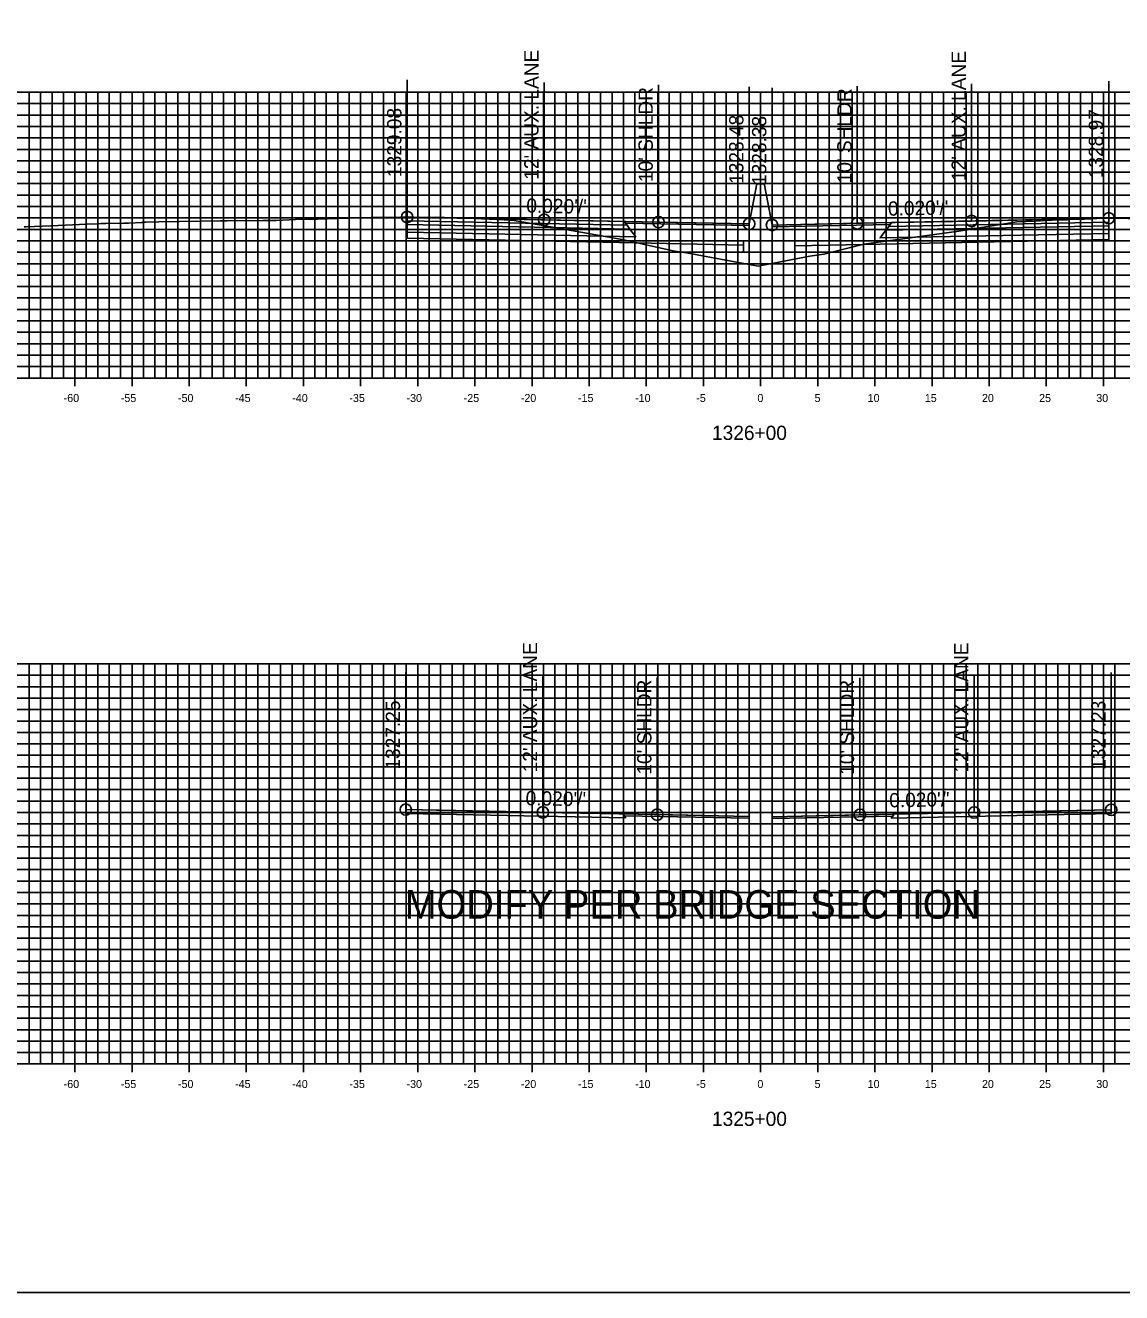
# Model space of a CAD drawing. Extents: x 674939 to 678919, y 750652 to 765176.
# Drawn here: x 678674.2 to 678770.1, y 751612.6 to 751723.4 of the extents above; entities that cross this region are included whole.
import ezdxf

# ---------------------------------------------------------------- set-up
doc = ezdxf.new("R2010")
doc.units = 0
for name, color, linetype in [('R_Alt Surface', 7, 'Continuous'), ('R_Axis', 7, 'Continuous'), ('R_Axis Annot', 7, 'Continuous'), ('R_Exist Surface', 7, 'Continuous'), ('R_Fin Surface', 7, 'Continuous'), ('R_Grid', 7, 'Continuous'), ('R_No Plot', 7, 'Continuous'), ('R_Proposed Road', 7, 'Continuous'), ('R_Xsect Elev', 7, 'Continuous'), ('R_Xsect Slope', 7, 'Continuous')]:
    doc.layers.add(name, color=color, linetype=linetype)

msp = doc.modelspace()

# ---------------------------------------------------------------- linework, layer by layer
at = {"layer": 'R_Alt Surface'}
for points in [[(678707.6, 751706.3), (678707.6, 751705.97), (678727.1, 751705.58), (678726.85, 751705.92)], [(678707.6, 751705.97), (678707.6, 751705.31), (678727.6, 751704.91), (678727.1, 751705.58)], [(678768.99, 751705.86), (678768.99, 751705.2), (678748.99, 751704.8), (678749.49, 751705.47)], [(678768.99, 751706.19), (678768.99, 751705.86), (678749.49, 751705.47), (678749.74, 751705.81)]]:
    msp.add_lwpolyline(points, close=True, dxfattribs=at)
for points in [[(678707.6, 751705.31), (678707.6, 751704.77), (678727.6, 751704.37), (678737.03, 751704.18)], [(678768.99, 751705.2), (678768.99, 751704.66), (678748.99, 751704.26), (678741.53, 751704.11)]]:
    msp.add_lwpolyline(points, dxfattribs=at)
at = {"layer": 'R_Axis'}
for p, q in [((678638.53, 751692.55), (678838.53, 751692.55)), ((678678.53, 751691.85), (678678.53, 751693.25)), ((678683.53, 751691.85), (678683.53, 751693.25)), ((678688.53, 751691.85), (678688.53, 751693.25)), ((678693.53, 751691.85), (678693.53, 751693.25)), ((678698.53, 751691.85), (678698.53, 751693.25)), ((678703.53, 751691.85), (678703.53, 751693.25)), ((678708.53, 751691.85), (678708.53, 751693.25)), ((678713.53, 751691.85), (678713.53, 751693.25)), ((678718.53, 751691.85), (678718.53, 751693.25)), ((678723.53, 751691.85), (678723.53, 751693.25)), ((678728.53, 751691.85), (678728.53, 751693.25)), ((678733.53, 751691.85), (678733.53, 751693.25)), ((678738.53, 751691.85), (678738.53, 751693.25)), ((678743.53, 751691.85), (678743.53, 751693.25)), ((678748.53, 751691.85), (678748.53, 751693.25)), ((678753.53, 751691.85), (678753.53, 751693.25)), ((678758.53, 751691.85), (678758.53, 751693.25)), ((678763.53, 751691.85), (678763.53, 751693.25)), ((678768.53, 751691.85), (678768.53, 751693.25)), ((678638.53, 751632.55), (678838.53, 751632.55)), ((678678.53, 751631.85), (678678.53, 751633.25)), ((678683.53, 751631.85), (678683.53, 751633.25)), ((678688.53, 751631.85), (678688.53, 751633.25)), ((678693.53, 751631.85), (678693.53, 751633.25)), ((678698.53, 751631.85), (678698.53, 751633.25)), ((678703.53, 751631.85), (678703.53, 751633.25)), ((678708.53, 751631.85), (678708.53, 751633.25)), ((678713.53, 751631.85), (678713.53, 751633.25)), ((678718.53, 751631.85), (678718.53, 751633.25)), ((678723.53, 751631.85), (678723.53, 751633.25)), ((678728.53, 751631.85), (678728.53, 751633.25)), ((678733.53, 751631.85), (678733.53, 751633.25)), ((678738.53, 751631.85), (678738.53, 751633.25)), ((678743.53, 751631.85), (678743.53, 751633.25)), ((678748.53, 751631.85), (678748.53, 751633.25)), ((678753.53, 751631.85), (678753.53, 751633.25)), ((678758.53, 751631.85), (678758.53, 751633.25)), ((678763.53, 751631.85), (678763.53, 751633.25)), ((678768.53, 751631.85), (678768.53, 751633.25))]:
    msp.add_line(p, q, dxfattribs=at)
at = {"layer": 'R_Exist Surface'}
msp.add_lwpolyline([(678674.1, 751705.78), (678674.26, 751705.76), (678674.27, 751705.76), (678676.43, 751705.85), (678677.71, 751705.91), (678679.56, 751706), (678680.49, 751706.03), (678680.8, 751706.05), (678681.25, 751706.06), (678682.8, 751706.09), (678683.21, 751706.09), (678684.43, 751706.16), (678684.47, 751706.17), (678684.61, 751706.18), (678684.78, 751706.19), (678685.87, 751706.21), (678691.28, 751706.3), (678691.87, 751706.31), (678694.96, 751706.33), (678695.82, 751706.33), (678695.92, 751706.33), (678696.14, 751706.34), (678697.84, 751706.42), (678698.52, 751706.43), (678699.76, 751706.45), (678703.32, 751706.55), (678704.45, 751706.58), (678707.06, 751706.62), (678707.6, 751706.63), (678707.65, 751706.63), (678707.98, 751706.64), (678708.16, 751706.63), (678708.63, 751706.6), (678709.71, 751706.6), (678710.07, 751706.61), (678711.71, 751706.56), (678712.16, 751706.56), (678716.09, 751706.39), (678716.98, 751706.34), (678720.98, 751705.64), (678726.41, 751704.67), (678730.88, 751703.67), (678732.2, 751703.48), (678738.33, 751702.34), (678742.85, 751703.22), (678744.07, 751703.38), (678747.55, 751704.26), (678755.88, 751705.39), (678760.94, 751706.22), (678762.53, 751706.28), (678764.56, 751706.39), (678764.86, 751706.39), (678765.36, 751706.39), (678765.56, 751706.41), (678765.96, 751706.43), (678766.86, 751706.45), (678767.46, 751706.48), (678767.96, 751706.51), (678768.36, 751706.53), (678768.67, 751706.53), (678768.99, 751706.52), (678772.38, 751706.47)], dxfattribs=at)
at = {"layer": 'R_Fin Surface'}
for points in [[(678737.53, 751706.03), (678729.6, 751706.19), (678719.6, 751706.39), (678707.6, 751706.63)], [(678768.99, 751706.52), (678756.99, 751706.28), (678746.99, 751706.08), (678739.53, 751705.93)], [(678737.53, 751654.2), (678729.48, 751654.36), (678719.48, 751654.56), (678707.48, 751654.8)], [(678769.21, 751654.78), (678757.21, 751654.54), (678747.21, 751654.34), (678739.53, 751654.18)]]:
    msp.add_lwpolyline(points, dxfattribs=at)
for points in [[(678707.6, 751706.63), (678707.6, 751706.3), (678726.85, 751705.92), (678726.6, 751706.25)], [(678726.6, 751706.25), (678737.53, 751706.03), (678737.54, 751705.88), (678726.72, 751706.09)], [(678749.87, 751705.98), (678739.53, 751705.78), (678739.53, 751705.93), (678749.99, 751706.14)], [(678768.99, 751706.52), (678768.99, 751706.19), (678749.74, 751705.81), (678749.99, 751706.14)], [(678707.48, 751654.8), (678707.48, 751654.47), (678726.73, 751654.09), (678726.48, 751654.42)], [(678769.21, 751654.78), (678769.21, 751654.45), (678749.96, 751654.06), (678750.21, 751654.4)], [(678726.48, 751654.42), (678737.53, 751654.2), (678737.54, 751654.04), (678726.6, 751654.26)], [(678750.09, 751654.24), (678739.53, 751654.03), (678739.53, 751654.18), (678750.21, 751654.4)]]:
    msp.add_lwpolyline(points, close=True, dxfattribs=at)
at = {"layer": 'R_Grid'}
for p, q in [((678638.53, 751717.55), (678838.53, 751717.55)), ((678674.53, 751692.55), (678674.53, 751717.55)), ((678675.53, 751692.55), (678675.53, 751717.55)), ((678676.53, 751692.55), (678676.53, 751717.55)), ((678677.53, 751692.55), (678677.53, 751717.55)), ((678678.53, 751692.55), (678678.53, 751717.55)), ((678679.53, 751692.55), (678679.53, 751717.55)), ((678680.53, 751692.55), (678680.53, 751717.55)), ((678681.53, 751692.55), (678681.53, 751717.55)), ((678682.53, 751692.55), (678682.53, 751717.55)), ((678683.53, 751692.55), (678683.53, 751717.55)), ((678684.53, 751692.55), (678684.53, 751717.55)), ((678685.53, 751692.55), (678685.53, 751717.55)), ((678686.53, 751692.55), (678686.53, 751717.55)), ((678687.53, 751692.55), (678687.53, 751717.55)), ((678688.53, 751692.55), (678688.53, 751717.55)), ((678689.53, 751692.55), (678689.53, 751717.55)), ((678690.53, 751692.55), (678690.53, 751717.55)), ((678691.53, 751692.55), (678691.53, 751717.55)), ((678692.53, 751692.55), (678692.53, 751717.55)), ((678693.53, 751692.55), (678693.53, 751717.55)), ((678694.53, 751692.55), (678694.53, 751717.55)), ((678695.53, 751692.55), (678695.53, 751717.55)), ((678696.53, 751692.55), (678696.53, 751717.55)), ((678697.53, 751692.55), (678697.53, 751717.55)), ((678698.53, 751692.55), (678698.53, 751717.55)), ((678699.53, 751692.55), (678699.53, 751717.55)), ((678700.53, 751692.55), (678700.53, 751717.55)), ((678701.53, 751692.55), (678701.53, 751717.55)), ((678702.53, 751692.55), (678702.53, 751717.55)), ((678703.53, 751692.55), (678703.53, 751717.55)), ((678704.53, 751692.55), (678704.53, 751717.55)), ((678705.53, 751692.55), (678705.53, 751717.55)), ((678706.53, 751692.55), (678706.53, 751717.55)), ((678707.53, 751692.55), (678707.53, 751717.55)), ((678708.53, 751692.55), (678708.53, 751717.55)), ((678709.53, 751692.55), (678709.53, 751717.55)), ((678710.53, 751692.55), (678710.53, 751717.55)), ((678711.53, 751692.55), (678711.53, 751717.55)), ((678712.53, 751692.55), (678712.53, 751717.55)), ((678713.53, 751692.55), (678713.53, 751717.55)), ((678714.53, 751692.55), (678714.53, 751717.55)), ((678715.53, 751692.55), (678715.53, 751717.55)), ((678716.53, 751692.55), (678716.53, 751717.55)), ((678717.53, 751692.55), (678717.53, 751717.55)), ((678718.53, 751692.55), (678718.53, 751717.55)), ((678719.53, 751692.55), (678719.53, 751717.55)), ((678720.53, 751692.55), (678720.53, 751717.55)), ((678721.53, 751692.55), (678721.53, 751717.55)), ((678722.53, 751692.55), (678722.53, 751717.55)), ((678723.53, 751692.55), (678723.53, 751717.55)), ((678724.53, 751692.55), (678724.53, 751717.55)), ((678725.53, 751692.55), (678725.53, 751717.55)), ((678726.53, 751692.55), (678726.53, 751717.55)), ((678727.53, 751692.55), (678727.53, 751717.55)), ((678728.53, 751692.55), (678728.53, 751717.55)), ((678729.53, 751692.55), (678729.53, 751717.55)), ((678730.53, 751692.55), (678730.53, 751717.55)), ((678731.53, 751692.55), (678731.53, 751717.55)), ((678732.53, 751692.55), (678732.53, 751717.55)), ((678733.53, 751692.55), (678733.53, 751717.55)), ((678734.53, 751692.55), (678734.53, 751717.55)), ((678735.53, 751692.55), (678735.53, 751717.55)), ((678736.53, 751692.55), (678736.53, 751717.55)), ((678737.53, 751692.55), (678737.53, 751717.55)), ((678738.53, 751692.55), (678738.53, 751717.55)), ((678739.53, 751692.55), (678739.53, 751717.55)), ((678740.53, 751692.55), (678740.53, 751717.55)), ((678741.53, 751692.55), (678741.53, 751717.55)), ((678742.53, 751692.55), (678742.53, 751717.55)), ((678743.53, 751692.55), (678743.53, 751717.55)), ((678744.53, 751692.55), (678744.53, 751717.55)), ((678745.53, 751692.55), (678745.53, 751717.55)), ((678746.53, 751692.55), (678746.53, 751717.55)), ((678747.53, 751692.55), (678747.53, 751717.55)), ((678748.53, 751692.55), (678748.53, 751717.55)), ((678749.53, 751692.55), (678749.53, 751717.55)), ((678750.53, 751692.55), (678750.53, 751717.55)), ((678751.53, 751692.55), (678751.53, 751717.55)), ((678752.53, 751692.55), (678752.53, 751717.55)), ((678753.53, 751692.55), (678753.53, 751717.55)), ((678754.53, 751692.55), (678754.53, 751717.55)), ((678755.53, 751692.55), (678755.53, 751717.55)), ((678756.53, 751692.55), (678756.53, 751717.55)), ((678757.53, 751692.55), (678757.53, 751717.55)), ((678758.53, 751692.55), (678758.53, 751717.55)), ((678759.53, 751692.55), (678759.53, 751717.55)), ((678760.53, 751692.55), (678760.53, 751717.55)), ((678761.53, 751692.55), (678761.53, 751717.55)), ((678762.53, 751692.55), (678762.53, 751717.55)), ((678763.53, 751692.55), (678763.53, 751717.55)), ((678764.53, 751692.55), (678764.53, 751717.55)), ((678765.53, 751692.55), (678765.53, 751717.55)), ((678766.53, 751692.55), (678766.53, 751717.55)), ((678767.53, 751692.55), (678767.53, 751717.55)), ((678768.53, 751692.55), (678768.53, 751717.55)), ((678769.53, 751692.55), (678769.53, 751717.55)), ((678638.53, 751716.55), (678838.53, 751716.55)), ((678638.53, 751715.55), (678838.53, 751715.55)), ((678638.53, 751714.55), (678838.53, 751714.55)), ((678638.53, 751713.55), (678838.53, 751713.55)), ((678638.53, 751712.55), (678838.53, 751712.55)), ((678638.53, 751711.55), (678838.53, 751711.55)), ((678638.53, 751710.55), (678838.53, 751710.55)), ((678638.53, 751709.55), (678838.53, 751709.55)), ((678638.53, 751708.55), (678838.53, 751708.55)), ((678638.53, 751707.55), (678838.53, 751707.55)), ((678638.53, 751706.55), (678838.53, 751706.55)), ((678638.53, 751705.55), (678838.53, 751705.55)), ((678638.53, 751704.55), (678838.53, 751704.55)), ((678638.53, 751703.55), (678838.53, 751703.55)), ((678638.53, 751702.55), (678838.53, 751702.55)), ((678638.53, 751701.55), (678838.53, 751701.55)), ((678638.53, 751700.55), (678838.53, 751700.55)), ((678638.53, 751699.55), (678838.53, 751699.55)), ((678638.53, 751698.55), (678838.53, 751698.55)), ((678638.53, 751697.55), (678838.53, 751697.55)), ((678638.53, 751696.55), (678838.53, 751696.55)), ((678638.53, 751695.55), (678838.53, 751695.55)), ((678638.53, 751694.55), (678838.53, 751694.55)), ((678638.53, 751693.55), (678838.53, 751693.55)), ((678638.53, 751692.55), (678838.53, 751692.55)), ((678638.53, 751667.55), (678838.53, 751667.55)), ((678674.53, 751632.55), (678674.53, 751667.55)), ((678675.53, 751632.55), (678675.53, 751667.55)), ((678676.53, 751632.55), (678676.53, 751667.55)), ((678677.53, 751632.55), (678677.53, 751667.55)), ((678678.53, 751632.55), (678678.53, 751667.55)), ((678679.53, 751632.55), (678679.53, 751667.55)), ((678680.53, 751632.55), (678680.53, 751667.55)), ((678681.53, 751632.55), (678681.53, 751667.55)), ((678682.53, 751632.55), (678682.53, 751667.55)), ((678683.53, 751632.55), (678683.53, 751667.55)), ((678684.53, 751632.55), (678684.53, 751667.55)), ((678685.53, 751632.55), (678685.53, 751667.55)), ((678686.53, 751632.55), (678686.53, 751667.55)), ((678687.53, 751632.55), (678687.53, 751667.55)), ((678688.53, 751632.55), (678688.53, 751667.55)), ((678689.53, 751632.55), (678689.53, 751667.55)), ((678690.53, 751632.55), (678690.53, 751667.55)), ((678691.53, 751632.55), (678691.53, 751667.55)), ((678692.53, 751632.55), (678692.53, 751667.55)), ((678693.53, 751632.55), (678693.53, 751667.55)), ((678694.53, 751632.55), (678694.53, 751667.55)), ((678695.53, 751632.55), (678695.53, 751667.55)), ((678696.53, 751632.55), (678696.53, 751667.55)), ((678697.53, 751632.55), (678697.53, 751667.55)), ((678698.53, 751632.55), (678698.53, 751667.55)), ((678699.53, 751632.55), (678699.53, 751667.55)), ((678700.53, 751632.55), (678700.53, 751667.55)), ((678701.53, 751632.55), (678701.53, 751667.55)), ((678702.53, 751632.55), (678702.53, 751667.55)), ((678703.53, 751632.55), (678703.53, 751667.55)), ((678704.53, 751632.55), (678704.53, 751667.55)), ((678705.53, 751632.55), (678705.53, 751667.55)), ((678706.53, 751632.55), (678706.53, 751667.55)), ((678707.53, 751632.55), (678707.53, 751667.55)), ((678708.53, 751632.55), (678708.53, 751667.55)), ((678709.53, 751632.55), (678709.53, 751667.55)), ((678710.53, 751632.55), (678710.53, 751667.55)), ((678711.53, 751632.55), (678711.53, 751667.55)), ((678712.53, 751632.55), (678712.53, 751667.55)), ((678713.53, 751632.55), (678713.53, 751667.55)), ((678714.53, 751632.55), (678714.53, 751667.55)), ((678715.53, 751632.55), (678715.53, 751667.55)), ((678716.53, 751632.55), (678716.53, 751667.55)), ((678717.53, 751632.55), (678717.53, 751667.55)), ((678718.53, 751632.55), (678718.53, 751667.55)), ((678719.53, 751632.55), (678719.53, 751667.55)), ((678720.53, 751632.55), (678720.53, 751667.55)), ((678721.53, 751632.55), (678721.53, 751667.55)), ((678722.53, 751632.55), (678722.53, 751667.55)), ((678723.53, 751632.55), (678723.53, 751667.55)), ((678724.53, 751632.55), (678724.53, 751667.55)), ((678725.53, 751632.55), (678725.53, 751667.55)), ((678726.53, 751632.55), (678726.53, 751667.55)), ((678727.53, 751632.55), (678727.53, 751667.55)), ((678728.53, 751632.55), (678728.53, 751667.55)), ((678729.53, 751632.55), (678729.53, 751667.55)), ((678730.53, 751632.55), (678730.53, 751667.55)), ((678731.53, 751632.55), (678731.53, 751667.55)), ((678732.53, 751632.55), (678732.53, 751667.55)), ((678733.53, 751632.55), (678733.53, 751667.55)), ((678734.53, 751632.55), (678734.53, 751667.55)), ((678735.53, 751632.55), (678735.53, 751667.55)), ((678736.53, 751632.55), (678736.53, 751667.55)), ((678737.53, 751632.55), (678737.53, 751667.55)), ((678738.53, 751632.55), (678738.53, 751667.55)), ((678739.53, 751632.55), (678739.53, 751667.55)), ((678740.53, 751632.55), (678740.53, 751667.55)), ((678741.53, 751632.55), (678741.53, 751667.55)), ((678742.53, 751632.55), (678742.53, 751667.55)), ((678743.53, 751632.55), (678743.53, 751667.55)), ((678744.53, 751632.55), (678744.53, 751667.55)), ((678745.53, 751632.55), (678745.53, 751667.55)), ((678746.53, 751632.55), (678746.53, 751667.55)), ((678747.53, 751632.55), (678747.53, 751667.55)), ((678748.53, 751632.55), (678748.53, 751667.55)), ((678749.53, 751632.55), (678749.53, 751667.55)), ((678750.53, 751632.55), (678750.53, 751667.55)), ((678751.53, 751632.55), (678751.53, 751667.55)), ((678752.53, 751632.55), (678752.53, 751667.55)), ((678753.53, 751632.55), (678753.53, 751667.55)), ((678754.53, 751632.55), (678754.53, 751667.55)), ((678755.53, 751632.55), (678755.53, 751667.55)), ((678756.53, 751632.55), (678756.53, 751667.55)), ((678757.53, 751632.55), (678757.53, 751667.55)), ((678758.53, 751632.55), (678758.53, 751667.55)), ((678759.53, 751632.55), (678759.53, 751667.55)), ((678760.53, 751632.55), (678760.53, 751667.55)), ((678761.53, 751632.55), (678761.53, 751667.55)), ((678762.53, 751632.55), (678762.53, 751667.55)), ((678763.53, 751632.55), (678763.53, 751667.55)), ((678764.53, 751632.55), (678764.53, 751667.55)), ((678765.53, 751632.55), (678765.53, 751667.55)), ((678766.53, 751632.55), (678766.53, 751667.55)), ((678767.53, 751632.55), (678767.53, 751667.55)), ((678768.53, 751632.55), (678768.53, 751667.55)), ((678769.53, 751632.55), (678769.53, 751667.55)), ((678638.53, 751666.55), (678838.53, 751666.55)), ((678638.53, 751665.55), (678838.53, 751665.55)), ((678638.53, 751664.55), (678838.53, 751664.55)), ((678638.53, 751663.55), (678838.53, 751663.55)), ((678638.53, 751662.55), (678838.53, 751662.55)), ((678638.53, 751661.55), (678838.53, 751661.55)), ((678638.53, 751660.55), (678838.53, 751660.55)), ((678638.53, 751659.55), (678838.53, 751659.55)), ((678638.53, 751658.55), (678838.53, 751658.55)), ((678638.53, 751657.55), (678838.53, 751657.55)), ((678638.53, 751656.55), (678838.53, 751656.55)), ((678638.53, 751655.55), (678838.53, 751655.55)), ((678638.53, 751654.55), (678838.53, 751654.55)), ((678638.53, 751653.55), (678838.53, 751653.55)), ((678638.53, 751652.55), (678838.53, 751652.55)), ((678638.53, 751651.55), (678838.53, 751651.55)), ((678638.53, 751650.55), (678838.53, 751650.55)), ((678638.53, 751649.55), (678838.53, 751649.55)), ((678638.53, 751648.55), (678838.53, 751648.55)), ((678638.53, 751647.55), (678838.53, 751647.55)), ((678638.53, 751646.55), (678838.53, 751646.55)), ((678638.53, 751645.55), (678838.53, 751645.55)), ((678638.53, 751644.55), (678838.53, 751644.55)), ((678638.53, 751643.55), (678838.53, 751643.55)), ((678638.53, 751642.55), (678838.53, 751642.55)), ((678638.53, 751641.55), (678838.53, 751641.55)), ((678638.53, 751640.55), (678838.53, 751640.55)), ((678638.53, 751639.55), (678838.53, 751639.55)), ((678638.53, 751638.55), (678838.53, 751638.55)), ((678638.53, 751637.55), (678838.53, 751637.55)), ((678638.53, 751636.55), (678838.53, 751636.55)), ((678638.53, 751635.55), (678838.53, 751635.55)), ((678638.53, 751634.55), (678838.53, 751634.55)), ((678638.53, 751633.55), (678838.53, 751633.55)), ((678638.53, 751632.55), (678838.53, 751632.55))]:
    msp.add_line(p, q, dxfattribs=at)
at = {"layer": 'R_No Plot'}
msp.add_lwpolyline([(678578.53, 751612.55), (678918.53, 751612.55), (678918.53, 751832.55), (678578.53, 751832.55)], close=True, dxfattribs=at)
for centre in [(678707.6, 751706.63), (678719.6, 751706.39), (678756.99, 751706.28), (678768.99, 751706.52), (678729.6, 751706.19), (678737.53, 751706.03), (678739.53, 751705.93), (678746.99, 751706.08), (678707.48, 751654.8), (678719.48, 751654.56), (678729.48, 751654.36), (678747.21, 751654.34), (678757.21, 751654.54), (678769.21, 751654.78)]:
    msp.add_circle(centre, 0.5, dxfattribs=at)
at = {"layer": 'R_Proposed Road'}
for points in [[(678738.2, 751709.53), (678737.53, 751706.03)], [(678738.86, 751709.43), (678738.86, 751709.53), (678738.2, 751709.53), (678738.2, 751709.53)], [(678738.86, 751709.43), (678739.53, 751705.93)], [(678737.53, 751706.03), (678737.53, 751704.56), (678737.03, 751704.56), (678737.03, 751703.56), (678741.53, 751703.56), (678741.53, 751704.56), (678739.53, 751704.56), (678739.53, 751705.93)]]:
    msp.add_lwpolyline(points, dxfattribs=at)
at = {"layer": 'R_Xsect Elev'}
for p, q in [((678707.6, 751706.63), (678707.6, 751718.63)), ((678719.6, 751706.39), (678719.6, 751718.39)), ((678729.6, 751706.19), (678729.6, 751718.19)), ((678737.53, 751706.03), (678737.53, 751718.03)), ((678739.53, 751705.93), (678739.53, 751717.93)), ((678746.99, 751706.08), (678746.99, 751718.08)), ((678756.99, 751706.28), (678756.99, 751718.28)), ((678768.99, 751706.52), (678768.99, 751718.52)), ((678707.48, 751654.8), (678707.48, 751666.8)), ((678719.48, 751654.56), (678719.48, 751666.56)), ((678729.48, 751654.36), (678729.48, 751666.36)), ((678747.21, 751654.34), (678747.21, 751666.34)), ((678757.21, 751654.54), (678757.21, 751666.54)), ((678769.21, 751654.78), (678769.21, 751666.78))]:
    msp.add_line(p, q, dxfattribs=at)

# ---------------------------------------------------------------- texts
at = {"layer": 'R_Axis Annot'}
for s, height, p in [('-60', 0.7, (678677.55, 751690.45)), ('-55', 0.7, (678682.55, 751690.45)), ('-50', 0.7, (678687.55, 751690.45)), ('-45', 0.7, (678692.55, 751690.45)), ('-40', 0.7, (678697.55, 751690.45)), ('-35', 0.7, (678702.55, 751690.45)), ('-30', 0.7, (678707.55, 751690.45)), ('-25', 0.7, (678712.55, 751690.45)), ('-20', 0.7, (678717.55, 751690.45)), ('-15', 0.7, (678722.55, 751690.45)), ('-10', 0.7, (678727.55, 751690.45)), ('-5', 0.7, (678732.9, 751690.45)), ('0', 0.7, (678738.25, 751690.45)), ('5', 0.7, (678743.25, 751690.45)), ('10', 0.7, (678747.9, 751690.45)), ('15', 0.7, (678752.9, 751690.45)), ('20', 0.7, (678757.9, 751690.45)), ('25', 0.7, (678762.9, 751690.45)), ('30', 0.7, (678767.9, 751690.45)), ('1326+00', 1.25, (678734.28, 751687.13)), ('-60', 0.7, (678677.55, 751630.45)), ('-55', 0.7, (678682.55, 751630.45)), ('-50', 0.7, (678687.55, 751630.45)), ('-45', 0.7, (678692.55, 751630.45)), ('-40', 0.7, (678697.55, 751630.45)), ('-35', 0.7, (678702.55, 751630.45)), ('-30', 0.7, (678707.55, 751630.45)), ('-25', 0.7, (678712.55, 751630.45)), ('-20', 0.7, (678717.55, 751630.45)), ('-15', 0.7, (678722.55, 751630.45)), ('-10', 0.7, (678727.55, 751630.45)), ('-5', 0.7, (678732.9, 751630.45)), ('0', 0.7, (678738.25, 751630.45)), ('5', 0.7, (678743.25, 751630.45)), ('10', 0.7, (678747.9, 751630.45)), ('15', 0.7, (678752.9, 751630.45)), ('20', 0.7, (678757.9, 751630.45)), ('25', 0.7, (678762.9, 751630.45)), ('30', 0.7, (678767.9, 751630.45)), ('1325+00', 1.25, (678734.28, 751627.13))]:
    msp.add_text(s, height=height, dxfattribs=at).set_placement(p)
at = {"layer": 'R_Xsect Elev'}
for s, p in [("12' AUX. LANE", (678719.1, 751709.89)), ("12' AUX. LANE", (678756.49, 751709.78)), ("10' SHLDR", (678729.1, 751709.69)), ("10' SHLDR", (678746.49, 751709.58)), ('1329.08', (678707.1, 751710.13)), ('1328.97', (678768.49, 751710.02)), ('1328.48', (678737.03, 751709.53)), ('1328.38', (678739.03, 751709.43)), ("12' AUX. LANE", (678718.98, 751658.06)), ("12' AUX. LANE", (678756.71, 751658.04)), ("10' SHLDR", (678728.98, 751657.86)), ("10' SHLDR", (678746.71, 751657.84)), ('1327.25', (678706.98, 751658.3)), ('1327.23', (678768.71, 751658.28))]:
    msp.add_text(s, height=1.25, rotation=90, dxfattribs=at).set_placement(p)
msp.add_text('MODIFY PER BRIDGE SECTION', height=2.5, dxfattribs=at).set_placement((678707.39, 751645.26))
at = {"layer": 'R_Xsect Slope'}
for rotation, p in [(358.8542, (678718.02, 751707.02)), (1.1458, (678749.69, 751706.74)), (358.8542, (678717.96, 751655.19)), (1.1458, (678749.8, 751654.99))]:
    msp.add_text("0.020'/'", height=1.25, rotation=rotation, dxfattribs=at).set_placement(p)

doc.saveas('drawing.dxf')
